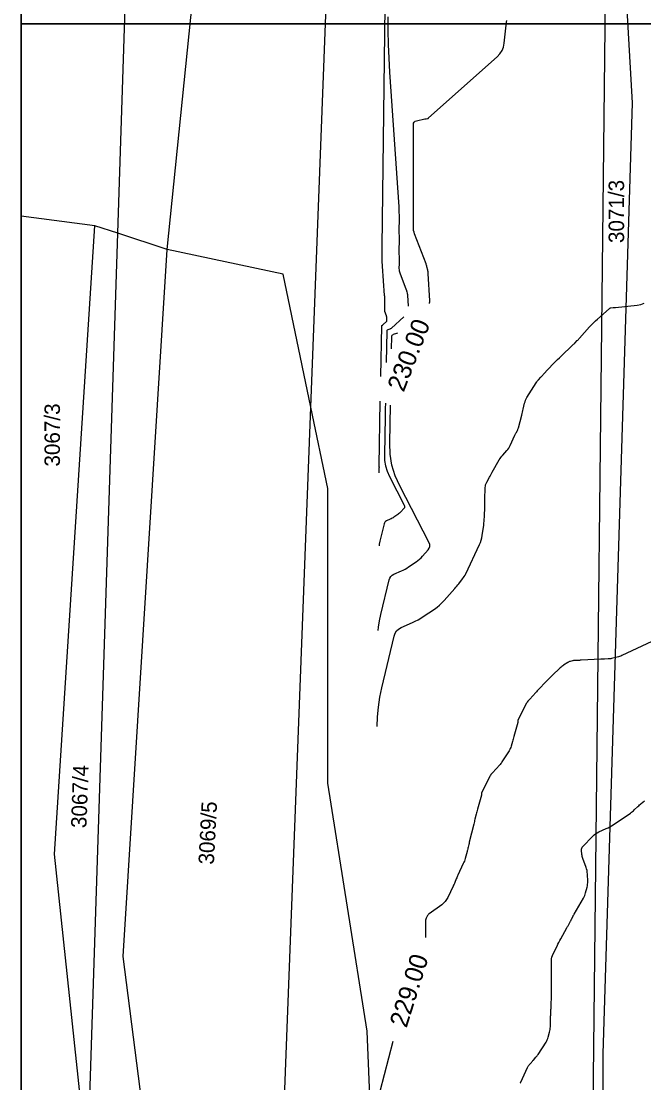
# Model space of a CAD drawing. Extents: x -534410 to -534262, y -1190162 to -1189584.
# Drawn here: x -534410.1 to -534375.9, y -1189747.8 to -1189689.3 of the extents above; entities that cross this region are included whole.
import ezdxf

# ---------------------------------------------------------------- set-up
doc = ezdxf.new("R2010")
doc.units = 0
for name, color, linetype in [('30', 7, 'Continuous'), ('31', 7, 'Continuous'), ('40', 7, 'Continuous'), ('_rámeček', 7, 'Continuous'), ('_rámeček_mřížka', 7, 'Continuous'), ('Hranice parcel', 7, 'Continuous'), ('Parcelní čísla', 7, 'Continuous')]:
    doc.layers.add(name, color=color, linetype=linetype)

msp = doc.modelspace()

# ---------------------------------------------------------------- linework, layer by layer
at = {"layer": '30'}
for points in [[(-534390.347, -1189708.884), (-534390.297, -1189706.091), (-534390.296, -1189706.085), (-534390.293, -1189706.08), (-534390.289, -1189706.076), (-534390.283, -1189706.073), (-534390.257, -1189706.064), (-534390.251, -1189706.061), (-534390.245, -1189706.058), (-534390.239, -1189706.054), (-534390.233, -1189706.05), (-534390.012, -1189705.849), (-534390.01, -1189705.846), (-534390.01, -1189705.836), (-534390.009, -1189705.834), (-534390.007, -1189705.824), (-534390.007, -1189705.818), (-534390.02, -1189705.611), (-534390.021, -1189705.605), (-534390.021, -1189705.599), (-534390.023, -1189705.592), (-534390.024, -1189705.586), (-534390.03, -1189705.562), (-534390.031, -1189705.556), (-534390.033, -1189705.55), (-534390.035, -1189705.544), (-534390.037, -1189705.538), (-534390.123, -1189705.312), (-534390.127, -1189705.298), (-534390.13, -1189705.285), (-534390.132, -1189705.271), (-534390.133, -1189705.257), (-534390.133, -1189705.161), (-534390.133, -1189705.109), (-534390.133, -1189704.996), (-534390.133, -1189704.885), (-534390.133, -1189704.834), (-534390.133, -1189704.721), (-534390.133, -1189704.61), (-534390.133, -1189704.558), (-534390.133, -1189704.487), (-534390.133, -1189704.473), (-534390.133, -1189704.459), (-534390.134, -1189704.445), (-534390.135, -1189704.431), (-534390.247, -1189702.817), (-534390.263, -1189702.543), (-534390.273, -1189702.269), (-534390.278, -1189701.995), (-534390.277, -1189701.721), (-534390.042, -1189684.12)], [(-534387.663, -1189704.868), (-534387.663, -1189704.864), (-534387.662, -1189704.854), (-534387.661, -1189704.845), (-534387.66, -1189704.835), (-534387.658, -1189704.825), (-534387.646, -1189704.767), (-534387.643, -1189704.754), (-534387.642, -1189704.741), (-534387.641, -1189704.728), (-534387.642, -1189704.715), (-534387.737, -1189703.209), (-534387.741, -1189703.164), (-534387.747, -1189703.118), (-534387.754, -1189703.073), (-534387.764, -1189703.029), (-534387.805, -1189702.851), (-534387.816, -1189702.806), (-534387.829, -1189702.762), (-534387.843, -1189702.719), (-534387.859, -1189702.676), (-534388.484, -1189701.034), (-534388.516, -1189700.939), (-534388.538, -1189700.841), (-534388.552, -1189700.742), (-534388.556, -1189700.641), (-534388.556, -1189700.125), (-534388.556, -1189700.032), (-534388.556, -1189699.938), (-534388.556, -1189699.704), (-534388.556, -1189699.611), (-534388.556, -1189699.564), (-534388.556, -1189699.048), (-534388.556, -1189698.946), (-534388.556, -1189698.845), (-534388.556, -1189698.743), (-534388.556, -1189698.641), (-534388.556, -1189698.125), (-534388.556, -1189698.032), (-534388.556, -1189697.938), (-534388.556, -1189697.704), (-534388.556, -1189697.611), (-534388.556, -1189697.564), (-534388.556, -1189697.048), (-534388.556, -1189696.946), (-534388.556, -1189696.845), (-534388.556, -1189696.743), (-534388.556, -1189696.641), (-534388.556, -1189696.125), (-534388.556, -1189696.032), (-534388.556, -1189695.938), (-534388.556, -1189695.704), (-534388.556, -1189695.611), (-534388.556, -1189695.564), (-534388.556, -1189695.016), (-534388.546, -1189694.938), (-534388.515, -1189694.878), (-534388.462, -1189694.835), (-534388.389, -1189694.808), (-534387.924, -1189694.707), (-534387.906, -1189694.704), (-534387.888, -1189694.7), (-534387.87, -1189694.697), (-534387.852, -1189694.694), (-534387.779, -1189694.683), (-534387.762, -1189694.68), (-534387.745, -1189694.673), (-534387.73, -1189694.665), (-534387.716, -1189694.654), (-534383.944, -1189691.283), (-534383.793, -1189691.123), (-534383.678, -1189690.944), (-534383.599, -1189690.747), (-534383.556, -1189690.532), (-534383.427, -1189689.383), (-534383.415, -1189689.283)], [(-534389.758, -1189707.367), (-534389.745, -1189706.698), (-534389.738, -1189706.652), (-534389.72, -1189706.614), (-534389.69, -1189706.584), (-534389.648, -1189706.563), (-534389.457, -1189706.496), (-534389.413, -1189706.478)], [(-534390.444, -1189714.199), (-534390.442, -1189713.921), (-534390.442, -1189713.914), (-534390.438, -1189713.899), (-534390.436, -1189713.897), (-534390.431, -1189713.895), (-534390.426, -1189713.891), (-534390.423, -1189713.887), (-534390.424, -1189713.886), (-534390.434, -1189713.865), (-534390.436, -1189713.862), (-534390.437, -1189713.858), (-534390.438, -1189713.854), (-534390.438, -1189713.85), (-534390.437, -1189713.799), (-534390.372, -1189710.252)], [(-534390.482, -1189722.874), (-534390.465, -1189722.694), (-534390.412, -1189722.337), (-534390.339, -1189721.983), (-534389.891, -1189720.084), (-534389.856, -1189719.981), (-534389.8, -1189719.895), (-534389.725, -1189719.825), (-534389.63, -1189719.771), (-534389.213, -1189719.588), (-534389.11, -1189719.54), (-534389.009, -1189719.488), (-534388.911, -1189719.431), (-534388.816, -1189719.369), (-534388.404, -1189719.089), (-534388.309, -1189719.02), (-534388.218, -1189718.945), (-534388.133, -1189718.865), (-534388.052, -1189718.779), (-534387.739, -1189718.424), (-534387.677, -1189718.333), (-534387.648, -1189718.238), (-534387.653, -1189718.139), (-534387.691, -1189718.036), (-534389.307, -1189714.911), (-534389.557, -1189714.347), (-534389.732, -1189713.765), (-534389.833, -1189713.165), (-534389.858, -1189712.549), (-534389.818, -1189710.468)], [(-534375.433, -1189723.48), (-534377.082, -1189724.25), (-534377.145, -1189724.277), (-534377.209, -1189724.302), (-534377.274, -1189724.323), (-534377.341, -1189724.34), (-534377.646, -1189724.413), (-534377.695, -1189724.423), (-534377.744, -1189724.431), (-534377.793, -1189724.436), (-534377.843, -1189724.438), (-534378.042, -1189724.444), (-534378.092, -1189724.445), (-534378.141, -1189724.447), (-534378.191, -1189724.449), (-534378.241, -1189724.451), (-534379.33, -1189724.51), (-534379.372, -1189724.512), (-534379.413, -1189724.514), (-534379.454, -1189724.515), (-534379.495, -1189724.517), (-534379.678, -1189724.522), (-534379.71, -1189724.523), (-534379.743, -1189724.527), (-534379.774, -1189724.533), (-534379.806, -1189724.541), (-534379.932, -1189724.576), (-534379.963, -1189724.585), (-534379.993, -1189724.598), (-534380.022, -1189724.612), (-534380.05, -1189724.628), (-534380.289, -1189724.782), (-534380.337, -1189724.814), (-534380.384, -1189724.849), (-534380.429, -1189724.886), (-534380.472, -1189724.925), (-534380.91, -1189725.339), (-534380.997, -1189725.422), (-534381.082, -1189725.506), (-534381.166, -1189725.591), (-534381.249, -1189725.678), (-534381.665, -1189726.118), (-534381.704, -1189726.159), (-534381.743, -1189726.201), (-534381.781, -1189726.243), (-534381.819, -1189726.285), (-534381.979, -1189726.464), (-534382.013, -1189726.502), (-534382.048, -1189726.54), (-534382.082, -1189726.578), (-534382.117, -1189726.616), (-534382.254, -1189726.768), (-534382.287, -1189726.807), (-534382.317, -1189726.848), (-534382.345, -1189726.891), (-534382.369, -1189726.936), (-534382.785, -1189727.762), (-534382.791, -1189727.776), (-534382.796, -1189727.79), (-534382.799, -1189727.804), (-534382.801, -1189727.819), (-534382.805, -1189727.879), (-534382.806, -1189727.893), (-534382.809, -1189727.908), (-534382.811, -1189727.923), (-534382.815, -1189727.937), (-534383.031, -1189728.712), (-534383.049, -1189728.778), (-534383.068, -1189728.845), (-534383.086, -1189728.911), (-534383.104, -1189728.977), (-534383.177, -1189729.241), (-534383.198, -1189729.306), (-534383.223, -1189729.369), (-534383.253, -1189729.43), (-534383.288, -1189729.489), (-534383.682, -1189730.105), (-534383.713, -1189730.152), (-534383.747, -1189730.198), (-534383.782, -1189730.243), (-534383.819, -1189730.286), (-534383.979, -1189730.464), (-534384.013, -1189730.502), (-534384.048, -1189730.54), (-534384.082, -1189730.578), (-534384.116, -1189730.616), (-534384.254, -1189730.768), (-534384.287, -1189730.807), (-534384.317, -1189730.848), (-534384.344, -1189730.891), (-534384.369, -1189730.936), (-534384.785, -1189731.762), (-534384.791, -1189731.776), (-534384.796, -1189731.79), (-534384.799, -1189731.804), (-534384.801, -1189731.819), (-534384.805, -1189731.879), (-534384.806, -1189731.893), (-534384.808, -1189731.908), (-534384.811, -1189731.923), (-534384.815, -1189731.937), (-534385.03, -1189732.709), (-534385.049, -1189732.777), (-534385.066, -1189732.845), (-534385.084, -1189732.913), (-534385.1, -1189732.981), (-534385.165, -1189733.253), (-534385.182, -1189733.322), (-534385.198, -1189733.39), (-534385.214, -1189733.458), (-534385.231, -1189733.526), (-534385.476, -1189734.53), (-534385.491, -1189734.593), (-534385.506, -1189734.656), (-534385.543, -1189734.807), (-534385.547, -1189734.826), (-534385.552, -1189734.844), (-534385.557, -1189734.863), (-534385.562, -1189734.882), (-534385.582, -1189734.958), (-534385.592, -1189734.995), (-534385.602, -1189735.033), (-534385.705, -1189735.424), (-534385.726, -1189735.495), (-534385.749, -1189735.565), (-534385.776, -1189735.633), (-534385.806, -1189735.701), (-534386.105, -1189736.336), (-534386.128, -1189736.386), (-534386.151, -1189736.436), (-534386.172, -1189736.487), (-534386.193, -1189736.538), (-534386.274, -1189736.742), (-534386.295, -1189736.793), (-534386.316, -1189736.844), (-534386.339, -1189736.894), (-534386.362, -1189736.944), (-534386.663, -1189737.567), (-534386.728, -1189737.683), (-534386.804, -1189737.787), (-534386.894, -1189737.882), (-534386.995, -1189737.966), (-534387.694, -1189738.476), (-534387.717, -1189738.496), (-534387.738, -1189738.517), (-534387.756, -1189738.541), (-534387.772, -1189738.567), (-534387.844, -1189738.704), (-534387.85, -1189738.717), (-534387.856, -1189738.73), (-534387.861, -1189738.744), (-534387.865, -1189738.758), (-534387.879, -1189738.816), (-534387.882, -1189738.83), (-534387.884, -1189738.845), (-534387.885, -1189738.859), (-534387.885, -1189738.874), (-534387.885, -1189739.769)], [(-534389.675, -1189745.496), (-534390.401, -1189748.249), (-534390.532, -1189748.817), (-534390.627, -1189749.39), (-534390.685, -1189749.968)]]:
    msp.add_lwpolyline(points, dxfattribs=at)
at = {"layer": '31'}
for points in [[(-534389.95, -1189689.079), (-534389.953, -1189689.842), (-534389.939, -1189690.605), (-534389.91, -1189691.367), (-534389.865, -1189692.129), (-534389.353, -1189699.537), (-534389.349, -1189699.594), (-534389.347, -1189699.652), (-534389.345, -1189699.71), (-534389.345, -1189699.767), (-534389.344, -1189700.088), (-534389.344, -1189700.168), (-534389.344, -1189700.327), (-534389.344, -1189700.38), (-534389.345, -1189700.674), (-534389.345, -1189700.732), (-534389.345, -1189700.79), (-534389.345, -1189700.847), (-534389.345, -1189700.905), (-534389.344, -1189701.225), (-534389.344, -1189701.305), (-534389.344, -1189701.465), (-534389.344, -1189701.518), (-534389.345, -1189701.812), (-534389.345, -1189701.869), (-534389.345, -1189701.927), (-534389.345, -1189701.985), (-534389.345, -1189702.043), (-534389.344, -1189702.363), (-534389.344, -1189702.443), (-534389.344, -1189702.603), (-534389.344, -1189702.656), (-534389.345, -1189702.949), (-534389.342, -1189703.007), (-534389.334, -1189703.063), (-534389.322, -1189703.119), (-534389.304, -1189703.173), (-534388.948, -1189704.107), (-534388.939, -1189704.131), (-534388.931, -1189704.156), (-534388.924, -1189704.181), (-534388.917, -1189704.206), (-534388.894, -1189704.308), (-534388.888, -1189704.333), (-534388.884, -1189704.359), (-534388.881, -1189704.384), (-534388.879, -1189704.41), (-534388.841, -1189705.007)], [(-534390.545, -1189728.162), (-534390.526, -1189727.621), (-534390.477, -1189727.083), (-534390.398, -1189726.549), (-534390.288, -1189726.018), (-534389.618, -1189723.176), (-534389.564, -1189723.023), (-534389.481, -1189722.893), (-534389.369, -1189722.788), (-534389.227, -1189722.708), (-534388.603, -1189722.434), (-534388.448, -1189722.362), (-534388.298, -1189722.284), (-534388.151, -1189722.198), (-534388.008, -1189722.106), (-534387.392, -1189721.688), (-534387.249, -1189721.584), (-534387.114, -1189721.472), (-534386.986, -1189721.352), (-534386.865, -1189721.223), (-534386.273, -1189720.552), (-534386.218, -1189720.489), (-534386.164, -1189720.424), (-534386.11, -1189720.359), (-534386.057, -1189720.293), (-534385.848, -1189720.029), (-534385.797, -1189719.961), (-534385.751, -1189719.891), (-534385.709, -1189719.819), (-534385.671, -1189719.744), (-534384.914, -1189718.143), (-534384.862, -1189718.021), (-534384.819, -1189717.896), (-534384.786, -1189717.768), (-534384.763, -1189717.637), (-534384.683, -1189717.063), (-534384.67, -1189716.953), (-534384.659, -1189716.844), (-534384.651, -1189716.734), (-534384.645, -1189716.625), (-534384.625, -1189716.024), (-534384.624, -1189715.994), (-534384.624, -1189715.964), (-534384.623, -1189715.934), (-534384.623, -1189715.904), (-534384.623, -1189715.785), (-534384.623, -1189715.755), (-534384.623, -1189715.725), (-534384.622, -1189715.695), (-534384.621, -1189715.665), (-534384.6, -1189715.001), (-534384.593, -1189714.924), (-534384.577, -1189714.849), (-534384.553, -1189714.777), (-534384.519, -1189714.708), (-534384.366, -1189714.435), (-534384.328, -1189714.367), (-534384.289, -1189714.298), (-534384.251, -1189714.23), (-534384.212, -1189714.162), (-534383.825, -1189713.479), (-534383.782, -1189713.408), (-534383.736, -1189713.34), (-534383.685, -1189713.275), (-534383.631, -1189713.212), (-534383.408, -1189712.967), (-534383.355, -1189712.904), (-534383.308, -1189712.837), (-534383.266, -1189712.767), (-534383.23, -1189712.693), (-534382.975, -1189712.114), (-534382.959, -1189712.08), (-534382.943, -1189712.047), (-534382.926, -1189712.015), (-534382.908, -1189711.983), (-534382.833, -1189711.855), (-534382.816, -1189711.823), (-534382.8, -1189711.79), (-534382.788, -1189711.756), (-534382.777, -1189711.721), (-534382.593, -1189711.007), (-534382.572, -1189710.926), (-534382.551, -1189710.844), (-534382.531, -1189710.763), (-534382.512, -1189710.681), (-534382.434, -1189710.355), (-534382.412, -1189710.275), (-534382.383, -1189710.197), (-534382.348, -1189710.122), (-534382.307, -1189710.05), (-534381.796, -1189709.229), (-534381.769, -1189709.187), (-534381.74, -1189709.146), (-534381.709, -1189709.107), (-534381.676, -1189709.069), (-534381.541, -1189708.919), (-534381.508, -1189708.882), (-534381.474, -1189708.845), (-534381.439, -1189708.808), (-534381.405, -1189708.772), (-534380.842, -1189708.178), (-534380.736, -1189708.068), (-534380.628, -1189707.959), (-534380.52, -1189707.852), (-534380.409, -1189707.746), (-534379.812, -1189707.179), (-534379.778, -1189707.146), (-534379.744, -1189707.113), (-534379.71, -1189707.08), (-534379.676, -1189707.046), (-534379.541, -1189706.912), (-534379.508, -1189706.878), (-534379.475, -1189706.844), (-534379.443, -1189706.809), (-534379.411, -1189706.774), (-534378.862, -1189706.158), (-534378.758, -1189706.046), (-534378.652, -1189705.936), (-534378.542, -1189705.829), (-534378.429, -1189705.726), (-534377.789, -1189705.154), (-534377.765, -1189705.136), (-534377.739, -1189705.122), (-534377.712, -1189705.112), (-534377.682, -1189705.107), (-534377.561, -1189705.094), (-534377.531, -1189705.091), (-534377.5, -1189705.088), (-534377.47, -1189705.084), (-534377.439, -1189705.081), (-534376.24, -1189704.963), (-534376.037, -1189704.926), (-534375.85, -1189704.857)], [(-534389.07, -1189705.596), (-534389.76, -1189706.222), (-534389.782, -1189706.241), (-534389.806, -1189706.256), (-534389.831, -1189706.269), (-534389.857, -1189706.28), (-534389.965, -1189706.318), (-534389.989, -1189706.33), (-534390.006, -1189706.347), (-534390.017, -1189706.368), (-534390.021, -1189706.395), (-534390.052, -1189708.124)], [(-534390.093, -1189710.361), (-534390.099, -1189710.657), (-534390.108, -1189711.11), (-534390.148, -1189713.199), (-534390.135, -1189713.51), (-534390.085, -1189713.811), (-534389.997, -1189714.104), (-534389.871, -1189714.388), (-534389.057, -1189715.961), (-534389.038, -1189716.013), (-534389.036, -1189716.063), (-534389.05, -1189716.11), (-534389.081, -1189716.156), (-534389.239, -1189716.335), (-534389.279, -1189716.378), (-534389.323, -1189716.419), (-534389.368, -1189716.456), (-534389.416, -1189716.491), (-534389.623, -1189716.632), (-534389.671, -1189716.663), (-534389.721, -1189716.692), (-534389.771, -1189716.718), (-534389.823, -1189716.742), (-534390.033, -1189716.834), (-534390.081, -1189716.861), (-534390.119, -1189716.897), (-534390.147, -1189716.94), (-534390.165, -1189716.992), (-534390.39, -1189717.947), (-534390.427, -1189718.126), (-534390.44, -1189718.216)], [(-534382.672, -1189747.784), (-534382.664, -1189747.77), (-534382.656, -1189747.756), (-534382.649, -1189747.742), (-534382.642, -1189747.728), (-534382.276, -1189746.925), (-534382.257, -1189746.885), (-534382.234, -1189746.848), (-534382.209, -1189746.813), (-534382.181, -1189746.779), (-534382.063, -1189746.649), (-534382.033, -1189746.616), (-534382.004, -1189746.584), (-534381.974, -1189746.551), (-534381.945, -1189746.518), (-534381.808, -1189746.366), (-534381.776, -1189746.329), (-534381.746, -1189746.291), (-534381.718, -1189746.251), (-534381.691, -1189746.211), (-534381.257, -1189745.532), (-534381.221, -1189745.469), (-534381.189, -1189745.404), (-534381.162, -1189745.337), (-534381.14, -1189745.268), (-534381.062, -1189744.986), (-534381.045, -1189744.915), (-534381.032, -1189744.843), (-534381.023, -1189744.771), (-534381.019, -1189744.698), (-534381.006, -1189744.227), (-534381.004, -1189744.166), (-534381.002, -1189744.104), (-534380.999, -1189744.042), (-534380.996, -1189743.981), (-534380.983, -1189743.734), (-534380.98, -1189743.673), (-534380.977, -1189743.611), (-534380.975, -1189743.55), (-534380.973, -1189743.488), (-534380.961, -1189743.036), (-534380.959, -1189742.94), (-534380.958, -1189742.844), (-534380.957, -1189742.749), (-534380.956, -1189742.653), (-534380.956, -1189742.111), (-534380.956, -1189741.951), (-534380.956, -1189741.631), (-534380.956, -1189741.525), (-534380.956, -1189741.041), (-534380.951, -1189740.944), (-534380.934, -1189740.85), (-534380.906, -1189740.758), (-534380.867, -1189740.669), (-534380.65, -1189740.241), (-534380.599, -1189740.14), (-534380.547, -1189740.04), (-534380.493, -1189739.941), (-534380.439, -1189739.842), (-534380.111, -1189739.248), (-534380.088, -1189739.208), (-534380.066, -1189739.167), (-534380.044, -1189739.127), (-534380.023, -1189739.087), (-534379.905, -1189738.869), (-534379.899, -1189738.857), (-534379.892, -1189738.844), (-534379.886, -1189738.832), (-534379.88, -1189738.819), (-534379.857, -1189738.768), (-534379.851, -1189738.756), (-534379.844, -1189738.743), (-534379.838, -1189738.73), (-534379.832, -1189738.718), (-534379.768, -1189738.593), (-534379.756, -1189738.568), (-534379.742, -1189738.543), (-534379.729, -1189738.518), (-534379.715, -1189738.494), (-534379.199, -1189737.61), (-534379.161, -1189737.539), (-534379.128, -1189737.466), (-534379.1, -1189737.391), (-534379.077, -1189737.314), (-534378.996, -1189737.001), (-534378.979, -1189736.922), (-534378.968, -1189736.843), (-534378.962, -1189736.763), (-534378.963, -1189736.683), (-534378.98, -1189736.278), (-534378.987, -1189736.184), (-534379.002, -1189736.092), (-534379.024, -1189736.001), (-534379.053, -1189735.911), (-534379.229, -1189735.429), (-534379.248, -1189735.373), (-534379.262, -1189735.316), (-534379.273, -1189735.258), (-534379.28, -1189735.199), (-534379.298, -1189734.963), (-534379.297, -1189734.906), (-534379.285, -1189734.853), (-534379.261, -1189734.804), (-534379.226, -1189734.759), (-534378.695, -1189734.203), (-534378.616, -1189734.128), (-534378.531, -1189734.061), (-534378.44, -1189734.003), (-534378.343, -1189733.954), (-534377.943, -1189733.774), (-534377.844, -1189733.726), (-534377.748, -1189733.675), (-534377.653, -1189733.62), (-534377.561, -1189733.561), (-534376.609, -1189732.919), (-534376.554, -1189732.881), (-534376.502, -1189732.84), (-534376.451, -1189732.797), (-534376.402, -1189732.752), (-534376.2, -1189732.558), (-534376.156, -1189732.517), (-534376.111, -1189732.476), (-534376.066, -1189732.436), (-534376.02, -1189732.397), (-534375.836, -1189732.242)]]:
    msp.add_lwpolyline(points, dxfattribs=at)
at = {"layer": '_rámeček'}
msp.add_line((-534410.126, -1189584.47), (-534410.126, -1190161.97), dxfattribs=at)
for points in [[(-534410.126, -1189584.47), (-534261.626, -1189584.47), (-534261.626, -1189689.47), (-534410.126, -1189689.47)], [(-534410.126, -1189689.47), (-534261.626, -1189689.47), (-534261.626, -1189794.47), (-534410.126, -1189794.47)]]:
    msp.add_lwpolyline(points, close=True, dxfattribs=at)
at = {"layer": '_rámeček_mřížka'}
for p, q in [((-534410.126, -1189584.47), (-534410.126, -1190161.97)), ((-534407.126, -1189689.47), (-534410.126, -1189689.47)), ((-534407.126, -1189689.47), (-534410.126, -1189689.47))]:
    msp.add_line(p, q, dxfattribs=at)
at = {"layer": 'Hranice parcel'}
for p, q in [((-534404.82, -1189701), (-534402.64, -1189633.7)), ((-534394.19, -1189710.57), (-534391.41, -1189637.73)), ((-534378.67, -1189750.28), (-534377.8, -1189671.05)), ((-534404.82, -1189701), (-534406.08, -1189700.59)), ((-534406.48, -1189752.31), (-534404.82, -1189701)), ((-534402.1, -1189701.89), (-534404.82, -1189701)), ((-534398.3, -1189817.87), (-534394.19, -1189710.57))]:
    msp.add_line(p, q, dxfattribs=at)
for points in [[(-534402.1, -1189701.89), (-534396.03, -1189642.33), (-534395.58, -1189636.23)], [(-534378.12, -1189750.26), (-534378.12, -1189746.17), (-534376.49, -1189693.82), (-534377.8, -1189671.05)], [(-534406.08, -1189700.59), (-534410.126, -1189700.066)], [(-534406.48, -1189752.31), (-534408.29, -1189735.19), (-534406.08, -1189700.59)], [(-534398.3, -1189817.87), (-534398.2, -1189776.76), (-534402.83, -1189754), (-534404.51, -1189740.82), (-534402.1, -1189701.89)], [(-534394.19, -1189710.57), (-534395.72, -1189703.26), (-534402.1, -1189701.89)], [(-534390.92, -1189749.37), (-534391.09, -1189744.93), (-534393.26, -1189731.27), (-534393.26, -1189715.05), (-534394.19, -1189710.57)]]:
    msp.add_lwpolyline(points, dxfattribs=at)

# ---------------------------------------------------------------- texts
at = {"layer": '40'}
for s, rotation, p in [('230.00', 68.76123, (-534389.089, -1189709.788)), ('229.00', 72.61335, (-534388.93, -1189744.788))]:
    msp.add_text(s, height=1, rotation=rotation, dxfattribs=at).set_placement(p)
at = {"layer": 'Parcelní čísla'}
for s, rotation, p in [('3071/3', 90, (-534376.962, -1189701.539)), ('3067/3', 90, (-534407.997, -1189713.846)), ('3067/4', 88, (-534406.541, -1189733.76)), ('3069/5', 87, (-534399.532, -1189735.774))]:
    msp.add_text(s, height=0.85, rotation=rotation, dxfattribs=at).set_placement(p)

doc.saveas('drawing.dxf')
